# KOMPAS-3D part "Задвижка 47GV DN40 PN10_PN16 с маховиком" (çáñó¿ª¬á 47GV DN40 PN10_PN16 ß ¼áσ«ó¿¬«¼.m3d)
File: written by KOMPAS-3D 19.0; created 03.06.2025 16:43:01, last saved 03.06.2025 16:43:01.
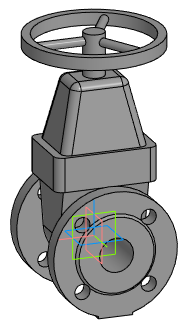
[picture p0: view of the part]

Document properties: Автор: Евгений; Полное имя файла: E:\Dendor Работа Сачек\3D для проекитирвщиков\2.1 Тип 47GV, 47GV.Z Задвижка клиновая фланцевая с обрезиненным клином\stp_Тип 47GV. Задвижка DN40-DN350 с маховиком\Задвижка 47GV DN40 PN10_PN16 с маховиком.m3d

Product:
- Part/product: Задвижка 47GV DN40 PN10_PN16 с маховиком

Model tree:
1. Операция без истории:1  (labels: Задвижка 47GV DN40 PN10_PN16 с маховиком)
